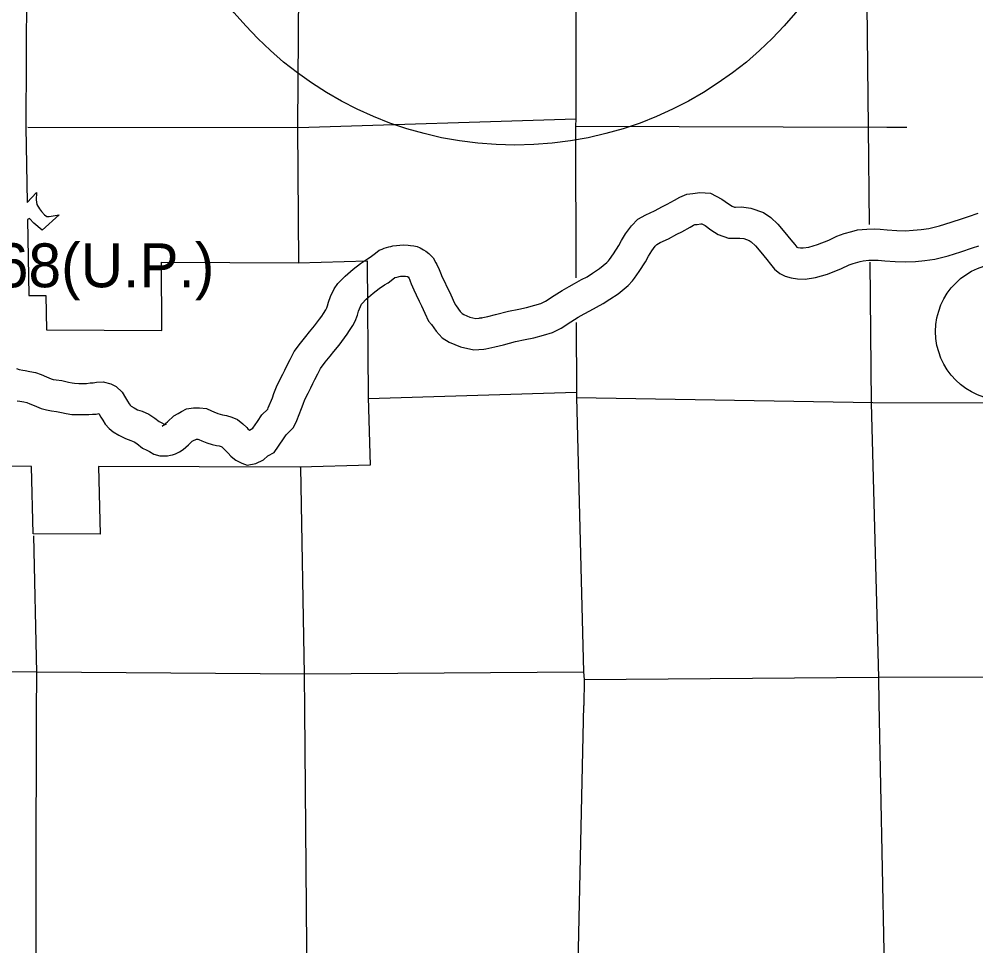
# Model space of a CAD drawing. Extents: x 77230 to 630905, y 790554 to 1662844.
# Drawn here: x 374822 to 393234, y 1590114 to 1607947 of the extents above; entities that cross this region are included whole.
import ezdxf

# ---------------------------------------------------------------- set-up
doc = ezdxf.new("R2010")
doc.units = 0
for name, color, linetype in [('Level 12', 7, 'Continuous'), ('Level 15', 7, 'Continuous'), ('Level 16', 7, 'Continuous'), ('Level 23', 7, 'Continuous'), ('Level 32', 7, 'Continuous'), ('Level 33', 7, 'Continuous'), ('Level 41', 7, 'Continuous')]:
    doc.layers.add(name, color=color, linetype=linetype)

msp = doc.modelspace()

# ---------------------------------------------------------------- linework, layer by layer
at = {"layer": 'Level 12'}
for points in [[(372720, 1608533), (374965, 1608540), (374954, 1605871), (374977, 1604421)], [(374977, 1604421), (375154, 1604608)], [(375154, 1604608), (375150, 1604468), (375165, 1604381), (375211, 1604297), (375255, 1604244), (375310, 1604181), (375356, 1604146), (375400, 1604146), (375594, 1604181), (375262, 1603883)], [(375262, 1603883), (375103, 1604020), (375020, 1604110), (374981, 1604093)], [(374981, 1604093), (375007, 1602628)], [(380192, 1603258), (381519, 1603295), (381542, 1600668), (381576, 1599365), (380225, 1599326), (376348, 1599336), (376381, 1598036), (375089, 1598045), (375059, 1599338), (373738, 1599344)], [(377566, 1601953), (377561, 1603273)], [(377561, 1603273), (380192, 1603258)], [(375007, 1602628), (375337, 1602626), (375348, 1601966)], [(375348, 1601966), (377566, 1601953)]]:
    msp.add_lwpolyline(points, dxfattribs=at)
at = {"layer": 'Level 15'}
for points in [[(385267, 1639924), (385279, 1637737), (385383, 1632387), (385503, 1627031), (385510, 1621895), (385558, 1616484), (385547, 1611299), (385541, 1611191), (385534, 1606026), (385527, 1605886), (385538, 1602969)], [(385541, 1602106), (385546, 1600766), (385546, 1600664), (385684, 1595389), (385694, 1595241), (385688, 1594740)], [(385737, 1570366), (385723, 1573779), (385728, 1574142), (385742, 1579119), (385724, 1579431), (385733, 1584779), (385590, 1589858), (385587, 1590060), (385688, 1594740)]]:
    msp.add_lwpolyline(points, dxfattribs=at)
at = {"layer": 'Level 16'}
for points in [[(380215, 1623725), (380246, 1621936), (380279, 1616649), (380219, 1611119), (380181, 1605874), (380196, 1603252)], [(391064, 1616452), (391104, 1611181), (391163, 1605867), (391183, 1603992)], [(374989, 1605866), (380191, 1605864), (385534, 1606026)], [(385527, 1605886), (391521, 1605865), (391908, 1605865)], [(391191, 1603270), (391221, 1600557), (391359, 1595280), (391369, 1594782)], [(381542, 1600648), (385546, 1600766)], [(385546, 1600664), (391248, 1600570), (396521, 1600563), (401768, 1600558), (402284, 1600561)], [(380235, 1599326), (380306, 1595334), (380314, 1594659)], [(375097, 1598001), (375155, 1595377), (375149, 1594584)], [(372230, 1595417), (375161, 1595385), (380321, 1595346), (385684, 1595389)], [(385694, 1595241), (391359, 1595284), (396587, 1595300), (401817, 1595291), (404810, 1595219)], [(391369, 1594782), (391463, 1590012), (391418, 1584708)], [(375149, 1594584), (375133, 1584892)], [(380314, 1594659), (380350, 1590095), (380458, 1584808), (380504, 1579303), (380538, 1574064), (380630, 1568872)]]:
    msp.add_lwpolyline(points, dxfattribs=at)
at = {"layer": 'Level 23'}
for p, q in [((383725, 1602197), (383683, 1602191)), ((383764, 1601598), (383806, 1601604)), ((377650, 1600154), (377572, 1600116)), ((377830, 1599582), (377908, 1599620))]:
    msp.add_line(p, q, dxfattribs=at)
for points in [[(383683, 1602191), (383841, 1602224), (383990, 1602262), (384240, 1602328), (384441, 1602367), (384587, 1602397), (384745, 1602440), (384864, 1602477), (384953, 1602522), (385116, 1602627), (385272, 1602726), (385407, 1602802), (385512, 1602858), (385645, 1602934), (385753, 1602990), (385858, 1603061), (385994, 1603149), (386131, 1603262), (386166, 1603299), (386182, 1603321), (386259, 1603428), (386361, 1603588), (386416, 1603685), (386494, 1603817), (386604, 1603972), (386730, 1604095), (386883, 1604181), (387052, 1604258), (387201, 1604340), (387296, 1604387), (387437, 1604464), (387536, 1604524), (387673, 1604577), (387785, 1604593), (387922, 1604611), (388130, 1604597), (388348, 1604482), (388471, 1604391), (388542, 1604347), (388587, 1604330), (388608, 1604330), (388724, 1604332), (388903, 1604311), (389147, 1604227), (389287, 1604127), (389423, 1604004), (389557, 1603844), (389674, 1603700), (389750, 1603608), (389787, 1603561), (389810, 1603555), (389861, 1603546), (389910, 1603545), (390022, 1603561), (390186, 1603607), (390402, 1603694), (390559, 1603773), (390701, 1603822), (390849, 1603860), (390955, 1603890), (391136, 1603905), (391279, 1603910), (391393, 1603905), (391529, 1603892), (391710, 1603880), (391877, 1603874), (392027, 1603884), (392184, 1603897), (392332, 1603917), (392537, 1603968), (392758, 1604039), (392978, 1604111), (393092, 1604151), (393275, 1604214)], [(383806, 1601604), (383977, 1601640), (384141, 1601682), (384374, 1601743), (384559, 1601779), (384726, 1601814), (384912, 1601864), (385089, 1601919), (385251, 1602000), (385440, 1602122), (385581, 1602211), (385696, 1602276), (385802, 1602333), (385932, 1602407), (386059, 1602473), (386188, 1602560), (386348, 1602664), (386544, 1602824), (386625, 1602912), (386665, 1602964), (386756, 1603092), (386875, 1603278), (386936, 1603386), (386998, 1603491), (387061, 1603580), (387093, 1603611), (387156, 1603646), (387321, 1603722), (387481, 1603809), (387575, 1603856), (387735, 1603944), (387800, 1603983), (387825, 1603992), (387868, 1603998), (387942, 1604008), (387963, 1604007), (388027, 1603973), (388134, 1603894), (388277, 1603805), (388475, 1603732), (388610, 1603730), (388694, 1603732), (388768, 1603723), (388869, 1603688), (388910, 1603659), (388990, 1603586), (389095, 1603463), (389209, 1603320), (389284, 1603230), (389360, 1603135), (389459, 1603054), (389566, 1602999), (389681, 1602968), (389804, 1602947), (389946, 1602944), (390145, 1602972), (390380, 1603038), (390649, 1603147), (390794, 1603219), (390873, 1603247), (391006, 1603281), (391063, 1603297), (391172, 1603306), (391277, 1603310), (391351, 1603307), (391480, 1603294), (391680, 1603281), (391886, 1603274), (392072, 1603285), (392249, 1603301), (392444, 1603327), (392702, 1603390), (392944, 1603469), (393170, 1603543), (393288, 1603584)], [(377572, 1600116), (377614, 1600145), (377677, 1600198), (377799, 1600315), (377880, 1600358), (377946, 1600394), (378040, 1600445), (378180, 1600470), (378294, 1600465), (378425, 1600455), (378523, 1600407), (378568, 1600389), (378643, 1600356), (378690, 1600343), (378734, 1600332), (378815, 1600320), (378913, 1600285), (379026, 1600245), (379127, 1600159), (379201, 1600088), (379221, 1600066), (379253, 1600039), (379322, 1600073), (379410, 1600204), (379495, 1600332), (379606, 1600442), (379617, 1600464), (379695, 1600660), (379721, 1600740), (379773, 1600873), (379848, 1601019), (379895, 1601116), (379935, 1601195), (379972, 1601276), (380035, 1601399), (380114, 1601549), (380239, 1601713), (380339, 1601837), (380412, 1601931), (380509, 1602044), (380601, 1602174), (380647, 1602234), (380678, 1602281), (380724, 1602352), (380743, 1602389), (380759, 1602428), (380776, 1602502), (380817, 1602608), (380886, 1602756), (380955, 1602860), (381096, 1603000), (381253, 1603134), (381393, 1603246), (381524, 1603333), (381575, 1603366), (381681, 1603446), (381751, 1603500), (381810, 1603521), (381849, 1603538), (381893, 1603550), (381936, 1603563), (381977, 1603573), (382016, 1603582), (382086, 1603594), (382146, 1603599), (382212, 1603601), (382307, 1603597), (382353, 1603592), (382418, 1603586), (382480, 1603569), (382537, 1603546), (382607, 1603508), (382646, 1603481), (382707, 1603437), (382787, 1603354), (382843, 1603258), (382863, 1603224), (382907, 1603130), (382929, 1603067), (382964, 1602980), (382999, 1602910), (383062, 1602782), (383109, 1602684), (383174, 1602540), (383216, 1602453), (383234, 1602429), (383312, 1602324), (383350, 1602281), (383378, 1602264), (383496, 1602214), (383614, 1602189), (383725, 1602197)], [(377908, 1599620), (377979, 1599667), (378079, 1599753), (378153, 1599824), (378162, 1599829), (378233, 1599867), (378234, 1599867), (378259, 1599866), (378264, 1599866), (378281, 1599858), (378337, 1599835), (378437, 1599791), (378536, 1599763), (378621, 1599742), (378669, 1599735), (378712, 1599720), (378721, 1599717), (378724, 1599714), (378766, 1599674), (378797, 1599638), (378846, 1599596), (378895, 1599539), (378934, 1599507), (378990, 1599459), (379109, 1599401), (379209, 1599364), (379380, 1599397), (379522, 1599465), (379606, 1599544), (379732, 1599607), (379909, 1599872), (379960, 1599949), (380103, 1600089), (380166, 1600223), (380259, 1600454), (380286, 1600537), (380322, 1600627), (380384, 1600751), (380433, 1600850), (380475, 1600935), (380512, 1601013), (380568, 1601123), (380622, 1601226), (380711, 1601343), (380809, 1601464), (380877, 1601552), (380982, 1601674), (381083, 1601817), (381136, 1601885), (381181, 1601953), (381244, 1602051), (381288, 1602137), (381334, 1602248), (381352, 1602328), (381369, 1602372), (381410, 1602461), (381421, 1602476), (381503, 1602558), (381636, 1602671), (381748, 1602761), (381855, 1602832), (381921, 1602875), (382043, 1602967), (382052, 1602972), (382060, 1602974), (382091, 1602983), (382114, 1602989), (382135, 1602994), (382161, 1602998), (382184, 1603000), (382210, 1603001), (382259, 1602999), (382289, 1602995), (382294, 1602995), (382301, 1602990), (382308, 1602985), (382326, 1602953), (382332, 1602944), (382350, 1602904), (382368, 1602853), (382417, 1602735), (382461, 1602644), (382523, 1602520), (382564, 1602433), (382630, 1602286), (382702, 1602137), (382755, 1602068), (382847, 1601943), (382963, 1601816), (383100, 1601731), (383315, 1601638), (383572, 1601585), (383764, 1601598)], [(374771, 1601221), (374824, 1601206), (374893, 1601193), (374938, 1601185), (375031, 1601169), (375136, 1601145), (375248, 1601107), (375349, 1601063), (375441, 1601025), (375476, 1601015), (375537, 1601006), (375643, 1600990), (375771, 1600964), (375845, 1600945), (375888, 1600939), (375969, 1600937), (376051, 1600937), (376118, 1600936), (376187, 1600947), (376249, 1600947), (376314, 1600959), (376441, 1600968), (376588, 1600927), (376689, 1600876), (376806, 1600767), (376870, 1600662), (376908, 1600597), (376940, 1600546), (376959, 1600516), (376962, 1600512), (376977, 1600500), (377036, 1600465), (377102, 1600430), (377190, 1600401), (377320, 1600343), (377434, 1600270), (377518, 1600204), (377558, 1600184), (377626, 1600147), (377627, 1600147), (377650, 1600154)], [(374785, 1600602), (374837, 1600594), (374913, 1600581), (374973, 1600567), (375031, 1600547), (375114, 1600511), (375245, 1600457), (375347, 1600428), (375447, 1600412), (375539, 1600399), (375637, 1600379), (375729, 1600356), (375839, 1600340), (375961, 1600337), (376047, 1600337), (376161, 1600336), (376235, 1600347), (376304, 1600348), (376354, 1600357), (376355, 1600355), (376394, 1600287), (376431, 1600228), (376480, 1600150), (376552, 1600072), (376632, 1600007), (376741, 1599942), (376867, 1599876), (376974, 1599840), (377035, 1599813), (377085, 1599781), (377195, 1599694), (377282, 1599651), (377332, 1599624), (377417, 1599574), (377529, 1599542), (377617, 1599541), (377677, 1599543), (377735, 1599556), (377772, 1599564), (377830, 1599582)]]:
    msp.add_lwpolyline(points, dxfattribs=at)
at = {"layer": 'Level 33'}
msp.add_circle((393779, 1601935), 1320, dxfattribs=at)
at = {"layer": 'Level 41'}
msp.add_circle((384364, 1612523), 7000, dxfattribs=at)

# ---------------------------------------------------------------- texts
at = {"layer": 'Level 32'}
msp.add_text('0.68(U.P.)', height=844.8, dxfattribs=at).set_placement((373431, 1602787))

doc.saveas('drawing.dxf')
